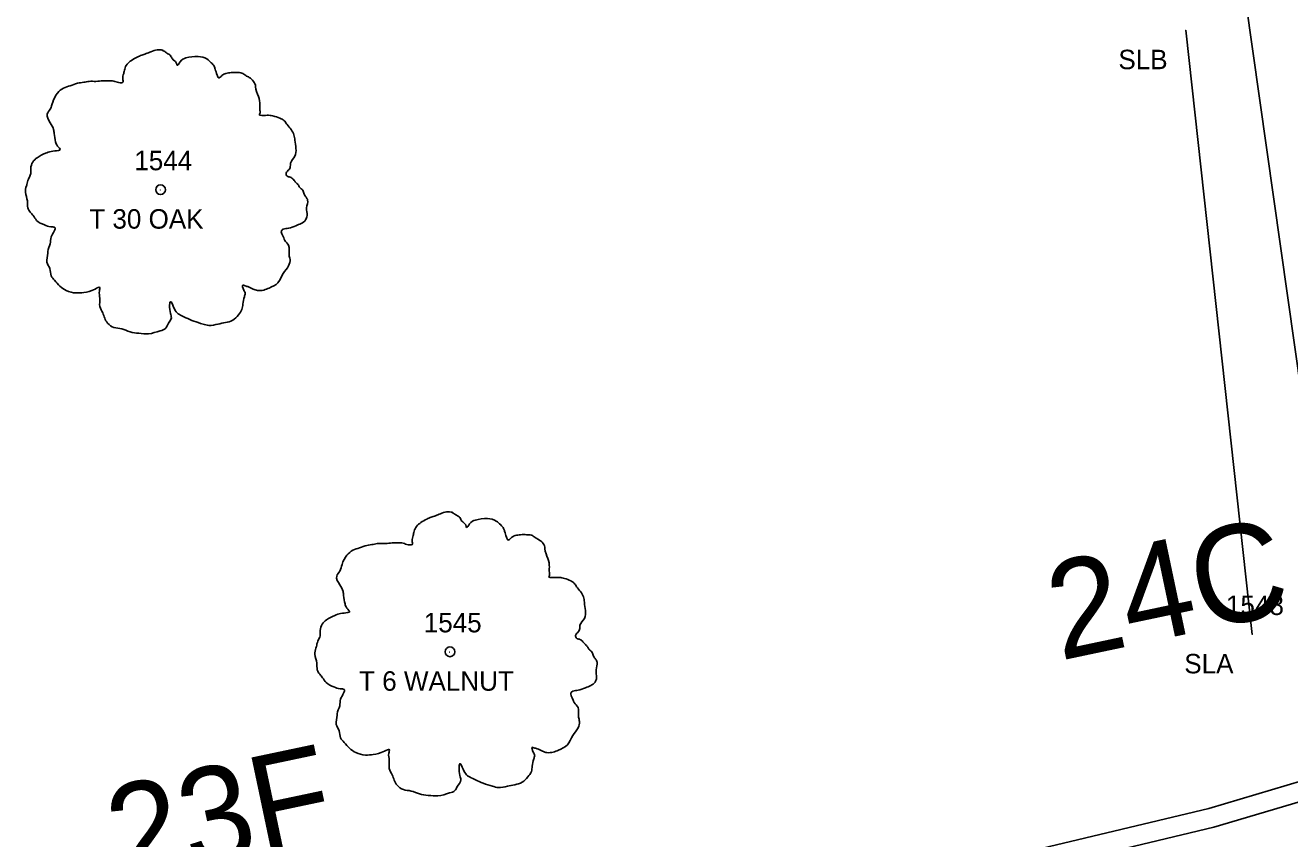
# Model space of a CAD drawing. Extents: x 1964982 to 1970452, y 1116335 to 1119906.
# Drawn here: x 1966511 to 1966576, y 1117422.5 to 1117464.3 of the extents above; entities that cross this region are included whole.
import ezdxf

# ---------------------------------------------------------------- set-up
doc = ezdxf.new("R2010")
doc.units = 0
for name, color, linetype in [('RD_EX_Driveway', 7, 'Continuous'), ('RD_EX_VEG', 7, 'Continuous'), ('RD_EX_VEG_txCode', 7, 'Continuous'), ('RD_PD_CstnLmt', 7, 'Continuous'), ('RD_PD_RW', 7, 'Continuous'), ('RD_PD_TX_CstnLmt', 7, 'Continuous'), ('RD_SMD_Locator', 7, 'Continuous')]:
    doc.layers.add(name, color=color, linetype=linetype)

msp = doc.modelspace()

# ---------------------------------------------------------------- linework, layer by layer
at = {"layer": 'RD_EX_Driveway'}
msp.add_lwpolyline([(1966578.028, 1117435.239), (1966571.581, 1117480.753), (1966567.97, 1117515.311), (1966576.556, 1117516.6), (1966582.112, 1117483.547), (1966603.624, 1117509.102), (1966634.749, 1117528.345), (1966662.085, 1117526.43), (1966689.524, 1117514.663), (1966711.523, 1117497.722), (1966730.008, 1117478.512), (1966744.031, 1117462.693), (1966734.107, 1117458.19)], dxfattribs=at)
at = {"layer": 'RD_EX_VEG'}
msp.add_line((1966574.062, 1117433.028), (1966570.646, 1117464.069), dxfattribs=at)
for centre, radius in [((1966517.984, 1117455.877), 0.25), ((1966517.984, 1117455.877), 0.25), ((1966517.971, 1117455.858), 0.0001), ((1966517.971, 1117455.858), 0.0001), ((1966532.852, 1117432.136), 0.25), ((1966532.852, 1117432.136), 0.25), ((1966532.839, 1117432.118), 0.0001), ((1966532.839, 1117432.118), 0.0001)]:
    msp.add_circle(centre, radius, dxfattribs=at)
for points in [[(1966518.116, 1117463.044), (1966517.816, 1117463.069), (1966517.491, 1117462.969), (1966517.241, 1117462.869), (1966517.016, 1117462.794), (1966516.791, 1117462.694), (1966516.491, 1117462.52), (1966516.266, 1117462.32), (1966516.141, 1117462.07), (1966516.091, 1117461.845), (1966516.041, 1117461.57), (1966516.041, 1117461.395), (1966515.917, 1117461.37), (1966515.767, 1117461.395), (1966515.517, 1117461.47), (1966515.267, 1117461.47), (1966515.017, 1117461.47), (1966514.667, 1117461.445), (1966514.317, 1117461.445), (1966514.042, 1117461.395), (1966513.717, 1117461.345), (1966513.343, 1117461.22), (1966512.993, 1117461.095), (1966512.693, 1117460.845), (1966512.443, 1117460.371), (1966512.318, 1117460.021), (1966512.168, 1117459.771), (1966512.318, 1117459.321), (1966512.493, 1117458.971), (1966512.518, 1117458.771), (1966512.593, 1117458.346), (1966512.693, 1117458.122), (1966512.818, 1117457.922), (1966512.743, 1117457.897), (1966512.368, 1117457.847), (1966512.068, 1117457.747), (1966511.643, 1117457.522), (1966511.418, 1117457.297), (1966511.318, 1117456.972), (1966511.294, 1117456.622), (1966511.194, 1117456.422), (1966511.119, 1117456.147), (1966511.094, 1117456.072), (1966511.044, 1117455.748), (1966511.144, 1117455.298), (1966511.169, 1117454.948), (1966511.294, 1117454.723), (1966511.443, 1117454.548), (1966511.618, 1117454.298), (1966512.018, 1117454.073), (1966512.343, 1117453.973), (1966512.543, 1117453.948), (1966512.368, 1117453.449), (1966512.318, 1117453.099), (1966512.193, 1117452.699), (1966512.193, 1117452.624), (1966512.143, 1117452.149), (1966512.293, 1117451.824), (1966512.368, 1117451.449), (1966512.543, 1117451.225), (1966512.818, 1117450.925), (1966513.143, 1117450.7), (1966513.643, 1117450.575), (1966514.042, 1117450.6), (1966514.617, 1117450.775), (1966514.867, 1117450.85), (1966514.842, 1117450.675), (1966514.867, 1117450.3), (1966514.867, 1117449.875), (1966515.017, 1117449.55), (1966515.117, 1117449.275), (1966515.267, 1117449.025), (1966515.592, 1117448.801), (1966515.991, 1117448.726), (1966516.416, 1117448.576), (1966516.866, 1117448.501), (1966517.366, 1117448.476), (1966517.966, 1117448.626), (1966518.24, 1117448.751), (1966518.34, 1117448.926), (1966518.54, 1117449.3), (1966518.49, 1117449.525), (1966518.515, 1117450.125), (1966518.615, 1117449.95), (1966518.79, 1117449.6), (1966519.29, 1117449.3), (1966519.69, 1117449.125), (1966520.165, 1117448.975), (1966520.465, 1117448.901), (1966520.939, 1117448.975), (1966521.314, 1117449.05), (1966521.689, 1117449.175), (1966521.989, 1117449.45), (1966522.164, 1117449.725), (1966522.214, 1117450), (1966522.289, 1117450.375), (1966522.339, 1117450.55)], [(1966518.116, 1117463.044), (1966517.816, 1117463.069), (1966517.491, 1117462.969), (1966517.241, 1117462.869), (1966517.016, 1117462.794), (1966516.791, 1117462.694), (1966516.491, 1117462.52), (1966516.266, 1117462.32), (1966516.141, 1117462.07), (1966516.091, 1117461.845), (1966516.041, 1117461.57), (1966516.041, 1117461.395), (1966515.917, 1117461.37), (1966515.767, 1117461.395), (1966515.517, 1117461.47), (1966515.267, 1117461.47), (1966515.017, 1117461.47), (1966514.667, 1117461.445), (1966514.317, 1117461.445), (1966514.042, 1117461.395), (1966513.717, 1117461.345), (1966513.343, 1117461.22), (1966512.993, 1117461.095), (1966512.693, 1117460.845), (1966512.443, 1117460.371), (1966512.318, 1117460.021), (1966512.168, 1117459.771), (1966512.318, 1117459.321), (1966512.493, 1117458.971), (1966512.518, 1117458.771), (1966512.593, 1117458.346), (1966512.693, 1117458.122), (1966512.818, 1117457.922), (1966512.743, 1117457.897), (1966512.368, 1117457.847), (1966512.068, 1117457.747), (1966511.643, 1117457.522), (1966511.418, 1117457.297), (1966511.318, 1117456.972), (1966511.294, 1117456.622), (1966511.194, 1117456.422), (1966511.119, 1117456.147), (1966511.094, 1117456.072), (1966511.044, 1117455.748), (1966511.144, 1117455.298), (1966511.169, 1117454.948), (1966511.294, 1117454.723), (1966511.443, 1117454.548), (1966511.618, 1117454.298), (1966512.018, 1117454.073), (1966512.343, 1117453.973), (1966512.543, 1117453.948), (1966512.368, 1117453.449), (1966512.318, 1117453.099), (1966512.193, 1117452.699), (1966512.193, 1117452.624), (1966512.143, 1117452.149), (1966512.293, 1117451.824), (1966512.368, 1117451.449), (1966512.543, 1117451.225), (1966512.818, 1117450.925), (1966513.143, 1117450.7), (1966513.643, 1117450.575), (1966514.042, 1117450.6), (1966514.617, 1117450.775), (1966514.867, 1117450.85), (1966514.842, 1117450.675), (1966514.867, 1117450.3), (1966514.867, 1117449.875), (1966515.017, 1117449.55), (1966515.117, 1117449.275), (1966515.267, 1117449.025), (1966515.592, 1117448.801), (1966515.991, 1117448.726), (1966516.416, 1117448.576), (1966516.866, 1117448.501), (1966517.366, 1117448.476), (1966517.966, 1117448.626), (1966518.24, 1117448.751), (1966518.34, 1117448.926), (1966518.54, 1117449.3), (1966518.49, 1117449.525), (1966518.515, 1117450.125), (1966518.615, 1117449.95), (1966518.79, 1117449.6), (1966519.29, 1117449.3), (1966519.69, 1117449.125), (1966520.165, 1117448.975), (1966520.465, 1117448.901), (1966520.939, 1117448.975), (1966521.314, 1117449.05), (1966521.689, 1117449.175), (1966521.989, 1117449.45), (1966522.164, 1117449.725), (1966522.214, 1117450), (1966522.289, 1117450.375), (1966522.339, 1117450.55)], [(1966522.339, 1117450.55), (1966522.264, 1117450.725), (1966522.214, 1117450.975), (1966522.289, 1117450.95), (1966522.464, 1117450.9), (1966522.739, 1117450.775), (1966522.963, 1117450.7), (1966523.288, 1117450.725), (1966523.563, 1117450.825), (1966524.013, 1117451.1), (1966524.288, 1117451.574), (1966524.563, 1117451.974), (1966524.638, 1117452.299), (1966524.588, 1117452.524), (1966524.563, 1117453.024), (1966524.363, 1117453.274), (1966524.313, 1117453.399), (1966524.213, 1117453.798), (1966524.288, 1117453.848), (1966524.563, 1117453.898), (1966524.938, 1117454.023), (1966525.212, 1117454.148), (1966525.437, 1117454.323), (1966525.512, 1117454.548), (1966525.487, 1117454.948), (1966525.537, 1117455.348), (1966525.462, 1117455.498), (1966525.362, 1117455.648), (1966525.287, 1117455.848), (1966525.137, 1117455.997), (1966525.038, 1117456.147), (1966524.938, 1117456.247), (1966524.813, 1117456.397), (1966524.638, 1117456.522), (1966524.488, 1117456.572), (1966524.438, 1117456.722), (1966524.588, 1117456.922), (1966524.638, 1117457.022), (1966524.663, 1117457.247), (1966524.888, 1117457.597), (1966524.938, 1117457.997), (1966524.888, 1117458.421), (1966524.838, 1117458.696), (1966524.688, 1117458.971), (1966524.488, 1117459.221), (1966524.363, 1117459.396), (1966524.188, 1117459.521), (1966523.863, 1117459.646), (1966523.613, 1117459.696), (1966523.263, 1117459.696), (1966523.063, 1117459.746), (1966523.088, 1117459.796), (1966523.088, 1117459.946), (1966523.088, 1117460.221), (1966523.013, 1117460.67), (1966522.863, 1117461.17), (1966522.863, 1117461.195), (1966522.763, 1117461.445), (1966522.539, 1117461.645), (1966522.364, 1117461.745), (1966522.164, 1117461.87), (1966521.914, 1117461.895), (1966521.614, 1117461.895), (1966521.339, 1117461.845), (1966521.139, 1117461.745), (1966520.964, 1117461.62), (1966520.889, 1117461.77), (1966520.789, 1117462.07), (1966520.739, 1117462.22), (1966520.589, 1117462.395), (1966520.365, 1117462.595), (1966519.915, 1117462.719), (1966519.29, 1117462.645), (1966518.99, 1117462.445), (1966518.84, 1117462.27), (1966518.79, 1117462.395), (1966518.59, 1117462.595), (1966518.49, 1117462.769), (1966518.315, 1117462.894), (1966518.166, 1117462.994), (1966518.066, 1117463.044)], [(1966522.339, 1117450.55), (1966522.264, 1117450.725), (1966522.214, 1117450.975), (1966522.289, 1117450.95), (1966522.464, 1117450.9), (1966522.739, 1117450.775), (1966522.963, 1117450.7), (1966523.288, 1117450.725), (1966523.563, 1117450.825), (1966524.013, 1117451.1), (1966524.288, 1117451.574), (1966524.563, 1117451.974), (1966524.638, 1117452.299), (1966524.588, 1117452.524), (1966524.563, 1117453.024), (1966524.363, 1117453.274), (1966524.313, 1117453.399), (1966524.213, 1117453.798), (1966524.288, 1117453.848), (1966524.563, 1117453.898), (1966524.938, 1117454.023), (1966525.212, 1117454.148), (1966525.437, 1117454.323), (1966525.512, 1117454.548), (1966525.487, 1117454.948), (1966525.537, 1117455.348), (1966525.462, 1117455.498), (1966525.362, 1117455.648), (1966525.287, 1117455.848), (1966525.137, 1117455.997), (1966525.038, 1117456.147), (1966524.938, 1117456.247), (1966524.813, 1117456.397), (1966524.638, 1117456.522), (1966524.488, 1117456.572), (1966524.438, 1117456.722), (1966524.588, 1117456.922), (1966524.638, 1117457.022), (1966524.663, 1117457.247), (1966524.888, 1117457.597), (1966524.938, 1117457.997), (1966524.888, 1117458.421), (1966524.838, 1117458.696), (1966524.688, 1117458.971), (1966524.488, 1117459.221), (1966524.363, 1117459.396), (1966524.188, 1117459.521), (1966523.863, 1117459.646), (1966523.613, 1117459.696), (1966523.263, 1117459.696), (1966523.063, 1117459.746), (1966523.088, 1117459.796), (1966523.088, 1117459.946), (1966523.088, 1117460.221), (1966523.013, 1117460.67), (1966522.863, 1117461.17), (1966522.863, 1117461.195), (1966522.763, 1117461.445), (1966522.539, 1117461.645), (1966522.364, 1117461.745), (1966522.164, 1117461.87), (1966521.914, 1117461.895), (1966521.614, 1117461.895), (1966521.339, 1117461.845), (1966521.139, 1117461.745), (1966520.964, 1117461.62), (1966520.889, 1117461.77), (1966520.789, 1117462.07), (1966520.739, 1117462.22), (1966520.589, 1117462.395), (1966520.365, 1117462.595), (1966519.915, 1117462.719), (1966519.29, 1117462.645), (1966518.99, 1117462.445), (1966518.84, 1117462.27), (1966518.79, 1117462.395), (1966518.59, 1117462.595), (1966518.49, 1117462.769), (1966518.315, 1117462.894), (1966518.166, 1117462.994), (1966518.066, 1117463.044)], [(1966532.984, 1117439.304), (1966532.684, 1117439.329), (1966532.359, 1117439.229), (1966532.109, 1117439.129), (1966531.884, 1117439.054), (1966531.659, 1117438.954), (1966531.359, 1117438.779), (1966531.135, 1117438.579), (1966531.01, 1117438.329), (1966530.96, 1117438.104), (1966530.91, 1117437.829), (1966530.91, 1117437.654), (1966530.785, 1117437.629), (1966530.635, 1117437.654), (1966530.385, 1117437.729), (1966530.135, 1117437.729), (1966529.885, 1117437.729), (1966529.535, 1117437.704), (1966529.185, 1117437.704), (1966528.911, 1117437.654), (1966528.586, 1117437.604), (1966528.211, 1117437.479), (1966527.861, 1117437.354), (1966527.561, 1117437.105), (1966527.311, 1117436.63), (1966527.186, 1117436.28), (1966527.036, 1117436.03), (1966527.186, 1117435.58), (1966527.361, 1117435.23), (1966527.386, 1117435.03), (1966527.461, 1117434.606), (1966527.561, 1117434.381), (1966527.686, 1117434.181), (1966527.611, 1117434.156), (1966527.236, 1117434.106), (1966526.936, 1117434.006), (1966526.512, 1117433.781), (1966526.287, 1117433.556), (1966526.187, 1117433.231), (1966526.162, 1117432.881), (1966526.062, 1117432.682), (1966525.987, 1117432.407), (1966525.962, 1117432.332), (1966525.912, 1117432.007), (1966526.012, 1117431.557), (1966526.037, 1117431.207), (1966526.162, 1117430.982), (1966526.312, 1117430.807), (1966526.487, 1117430.557), (1966526.886, 1117430.333), (1966527.211, 1117430.233), (1966527.411, 1117430.208), (1966527.236, 1117429.708), (1966527.186, 1117429.358), (1966527.061, 1117428.958), (1966527.061, 1117428.883), (1966527.011, 1117428.408), (1966527.161, 1117428.083), (1966527.236, 1117427.709), (1966527.411, 1117427.484), (1966527.686, 1117427.184), (1966528.011, 1117426.959), (1966528.511, 1117426.834), (1966528.911, 1117426.859), (1966529.485, 1117427.034), (1966529.735, 1117427.109), (1966529.71, 1117426.934), (1966529.735, 1117426.559), (1966529.735, 1117426.134), (1966529.885, 1117425.81), (1966529.985, 1117425.535), (1966530.135, 1117425.285), (1966530.46, 1117425.06), (1966530.86, 1117424.985), (1966531.284, 1117424.835), (1966531.734, 1117424.76), (1966532.234, 1117424.735), (1966532.834, 1117424.885), (1966533.109, 1117425.01), (1966533.209, 1117425.185), (1966533.409, 1117425.56), (1966533.359, 1117425.785), (1966533.384, 1117426.384), (1966533.483, 1117426.209), (1966533.658, 1117425.859), (1966534.158, 1117425.56), (1966534.558, 1117425.385), (1966535.033, 1117425.235), (1966535.333, 1117425.16), (1966535.807, 1117425.235), (1966536.182, 1117425.31), (1966536.557, 1117425.435), (1966536.857, 1117425.71), (1966537.032, 1117425.984), (1966537.082, 1117426.259), (1966537.157, 1117426.634), (1966537.207, 1117426.809)], [(1966532.984, 1117439.304), (1966532.684, 1117439.329), (1966532.359, 1117439.229), (1966532.109, 1117439.129), (1966531.884, 1117439.054), (1966531.659, 1117438.954), (1966531.359, 1117438.779), (1966531.135, 1117438.579), (1966531.01, 1117438.329), (1966530.96, 1117438.104), (1966530.91, 1117437.829), (1966530.91, 1117437.654), (1966530.785, 1117437.629), (1966530.635, 1117437.654), (1966530.385, 1117437.729), (1966530.135, 1117437.729), (1966529.885, 1117437.729), (1966529.535, 1117437.704), (1966529.185, 1117437.704), (1966528.911, 1117437.654), (1966528.586, 1117437.604), (1966528.211, 1117437.479), (1966527.861, 1117437.354), (1966527.561, 1117437.105), (1966527.311, 1117436.63), (1966527.186, 1117436.28), (1966527.036, 1117436.03), (1966527.186, 1117435.58), (1966527.361, 1117435.23), (1966527.386, 1117435.03), (1966527.461, 1117434.606), (1966527.561, 1117434.381), (1966527.686, 1117434.181), (1966527.611, 1117434.156), (1966527.236, 1117434.106), (1966526.936, 1117434.006), (1966526.512, 1117433.781), (1966526.287, 1117433.556), (1966526.187, 1117433.231), (1966526.162, 1117432.881), (1966526.062, 1117432.682), (1966525.987, 1117432.407), (1966525.962, 1117432.332), (1966525.912, 1117432.007), (1966526.012, 1117431.557), (1966526.037, 1117431.207), (1966526.162, 1117430.982), (1966526.312, 1117430.807), (1966526.487, 1117430.557), (1966526.886, 1117430.333), (1966527.211, 1117430.233), (1966527.411, 1117430.208), (1966527.236, 1117429.708), (1966527.186, 1117429.358), (1966527.061, 1117428.958), (1966527.061, 1117428.883), (1966527.011, 1117428.408), (1966527.161, 1117428.083), (1966527.236, 1117427.709), (1966527.411, 1117427.484), (1966527.686, 1117427.184), (1966528.011, 1117426.959), (1966528.511, 1117426.834), (1966528.911, 1117426.859), (1966529.485, 1117427.034), (1966529.735, 1117427.109), (1966529.71, 1117426.934), (1966529.735, 1117426.559), (1966529.735, 1117426.134), (1966529.885, 1117425.81), (1966529.985, 1117425.535), (1966530.135, 1117425.285), (1966530.46, 1117425.06), (1966530.86, 1117424.985), (1966531.284, 1117424.835), (1966531.734, 1117424.76), (1966532.234, 1117424.735), (1966532.834, 1117424.885), (1966533.109, 1117425.01), (1966533.209, 1117425.185), (1966533.409, 1117425.56), (1966533.359, 1117425.785), (1966533.384, 1117426.384), (1966533.483, 1117426.209), (1966533.658, 1117425.859), (1966534.158, 1117425.56), (1966534.558, 1117425.385), (1966535.033, 1117425.235), (1966535.333, 1117425.16), (1966535.807, 1117425.235), (1966536.182, 1117425.31), (1966536.557, 1117425.435), (1966536.857, 1117425.71), (1966537.032, 1117425.984), (1966537.082, 1117426.259), (1966537.157, 1117426.634), (1966537.207, 1117426.809)], [(1966537.207, 1117426.809), (1966537.132, 1117426.984), (1966537.082, 1117427.234), (1966537.157, 1117427.209), (1966537.332, 1117427.159), (1966537.607, 1117427.034), (1966537.832, 1117426.959), (1966538.156, 1117426.984), (1966538.431, 1117427.084), (1966538.881, 1117427.359), (1966539.156, 1117427.834), (1966539.431, 1117428.233), (1966539.506, 1117428.558), (1966539.456, 1117428.783), (1966539.431, 1117429.283), (1966539.231, 1117429.533), (1966539.181, 1117429.658), (1966539.081, 1117430.058), (1966539.156, 1117430.108), (1966539.431, 1117430.158), (1966539.806, 1117430.283), (1966540.081, 1117430.407), (1966540.306, 1117430.582), (1966540.38, 1117430.807), (1966540.356, 1117431.207), (1966540.405, 1117431.607), (1966540.331, 1117431.757), (1966540.231, 1117431.907), (1966540.156, 1117432.107), (1966540.006, 1117432.257), (1966539.906, 1117432.407), (1966539.806, 1117432.507), (1966539.681, 1117432.657), (1966539.506, 1117432.781), (1966539.356, 1117432.831), (1966539.306, 1117432.981), (1966539.456, 1117433.181), (1966539.506, 1117433.281), (1966539.531, 1117433.506), (1966539.756, 1117433.856), (1966539.806, 1117434.256), (1966539.756, 1117434.681), (1966539.706, 1117434.956), (1966539.556, 1117435.23), (1966539.356, 1117435.48), (1966539.231, 1117435.655), (1966539.056, 1117435.78), (1966538.731, 1117435.905), (1966538.481, 1117435.955), (1966538.131, 1117435.955), (1966537.932, 1117436.005), (1966537.957, 1117436.055), (1966537.957, 1117436.205), (1966537.957, 1117436.48), (1966537.882, 1117436.93), (1966537.732, 1117437.429), (1966537.732, 1117437.454), (1966537.632, 1117437.704), (1966537.407, 1117437.904), (1966537.232, 1117438.004), (1966537.032, 1117438.129), (1966536.782, 1117438.154), (1966536.482, 1117438.154), (1966536.207, 1117438.104), (1966536.007, 1117438.004), (1966535.832, 1117437.879), (1966535.757, 1117438.029), (1966535.658, 1117438.329), (1966535.608, 1117438.479), (1966535.458, 1117438.654), (1966535.233, 1117438.854), (1966534.783, 1117438.979), (1966534.158, 1117438.904), (1966533.858, 1117438.704), (1966533.708, 1117438.529), (1966533.658, 1117438.654), (1966533.458, 1117438.854), (1966533.359, 1117439.029), (1966533.184, 1117439.154), (1966533.034, 1117439.254), (1966532.934, 1117439.304)], [(1966537.207, 1117426.809), (1966537.132, 1117426.984), (1966537.082, 1117427.234), (1966537.157, 1117427.209), (1966537.332, 1117427.159), (1966537.607, 1117427.034), (1966537.832, 1117426.959), (1966538.156, 1117426.984), (1966538.431, 1117427.084), (1966538.881, 1117427.359), (1966539.156, 1117427.834), (1966539.431, 1117428.233), (1966539.506, 1117428.558), (1966539.456, 1117428.783), (1966539.431, 1117429.283), (1966539.231, 1117429.533), (1966539.181, 1117429.658), (1966539.081, 1117430.058), (1966539.156, 1117430.108), (1966539.431, 1117430.158), (1966539.806, 1117430.283), (1966540.081, 1117430.407), (1966540.306, 1117430.582), (1966540.38, 1117430.807), (1966540.356, 1117431.207), (1966540.405, 1117431.607), (1966540.331, 1117431.757), (1966540.231, 1117431.907), (1966540.156, 1117432.107), (1966540.006, 1117432.257), (1966539.906, 1117432.407), (1966539.806, 1117432.507), (1966539.681, 1117432.657), (1966539.506, 1117432.781), (1966539.356, 1117432.831), (1966539.306, 1117432.981), (1966539.456, 1117433.181), (1966539.506, 1117433.281), (1966539.531, 1117433.506), (1966539.756, 1117433.856), (1966539.806, 1117434.256), (1966539.756, 1117434.681), (1966539.706, 1117434.956), (1966539.556, 1117435.23), (1966539.356, 1117435.48), (1966539.231, 1117435.655), (1966539.056, 1117435.78), (1966538.731, 1117435.905), (1966538.481, 1117435.955), (1966538.131, 1117435.955), (1966537.932, 1117436.005), (1966537.957, 1117436.055), (1966537.957, 1117436.205), (1966537.957, 1117436.48), (1966537.882, 1117436.93), (1966537.732, 1117437.429), (1966537.732, 1117437.454), (1966537.632, 1117437.704), (1966537.407, 1117437.904), (1966537.232, 1117438.004), (1966537.032, 1117438.129), (1966536.782, 1117438.154), (1966536.482, 1117438.154), (1966536.207, 1117438.104), (1966536.007, 1117438.004), (1966535.832, 1117437.879), (1966535.757, 1117438.029), (1966535.658, 1117438.329), (1966535.608, 1117438.479), (1966535.458, 1117438.654), (1966535.233, 1117438.854), (1966534.783, 1117438.979), (1966534.158, 1117438.904), (1966533.858, 1117438.704), (1966533.708, 1117438.529), (1966533.658, 1117438.654), (1966533.458, 1117438.854), (1966533.359, 1117439.029), (1966533.184, 1117439.154), (1966533.034, 1117439.254), (1966532.934, 1117439.304)]]:
    msp.add_spline(points, degree=3, dxfattribs=at)
at = {"layer": 'RD_PD_CstnLmt'}
for p, q in [((1966619.782, 1117437.316), (1966572.088, 1117423.122)), ((1966572.088, 1117423.122), (1966523.43, 1117411.54))]:
    msp.add_line(p, q, dxfattribs=at)
at = {"layer": 'RD_PD_RW'}
for p, q in [((1966619.521, 1117438.281), (1966571.829, 1117424.088)), ((1966571.829, 1117424.088), (1966523.251, 1117412.525))]:
    msp.add_line(p, q, dxfattribs=at)
at = {"layer": 'RD_SMD_Locator'}
for centre in [(1966570.646, 1117464.069), (1966570.646, 1117464.069), (1966574.062, 1117433.028), (1966574.062, 1117433.028)]:
    msp.add_circle(centre, 0.001, dxfattribs=at)

# ---------------------------------------------------------------- texts
at = {"layer": 'RD_EX_VEG_txCode'}
for s, p in [('SLB', (1966567.189, 1117462.069)), ('SLB', (1966567.189, 1117462.069)), ('1544', (1966516.637, 1117456.877)), ('1544', (1966516.637, 1117456.877)), ('T 30 OAK', (1966514.322, 1117453.877)), ('T 30 OAK', (1966514.322, 1117453.877)), ('1548', (1966572.716, 1117434.028)), ('1548', (1966572.716, 1117434.028)), ('1545', (1966531.505, 1117433.136)), ('1545', (1966531.505, 1117433.136)), ('SLA', (1966570.574, 1117431.028)), ('SLA', (1966570.574, 1117431.028)), ('T 6 WALNUT', (1966528.183, 1117430.136)), ('T 6 WALNUT', (1966528.183, 1117430.136))]:
    msp.add_text(s, height=1, dxfattribs=at).set_placement(p)
at = {"layer": 'RD_PD_TX_CstnLmt'}
for s, p in [('24C', (1966564.184, 1117431.675)), ('23F', (1966515.876, 1117420.167))]:
    msp.add_text(s, height=5, rotation=11.90472, dxfattribs=at).set_placement(p)

doc.saveas('drawing.dxf')
